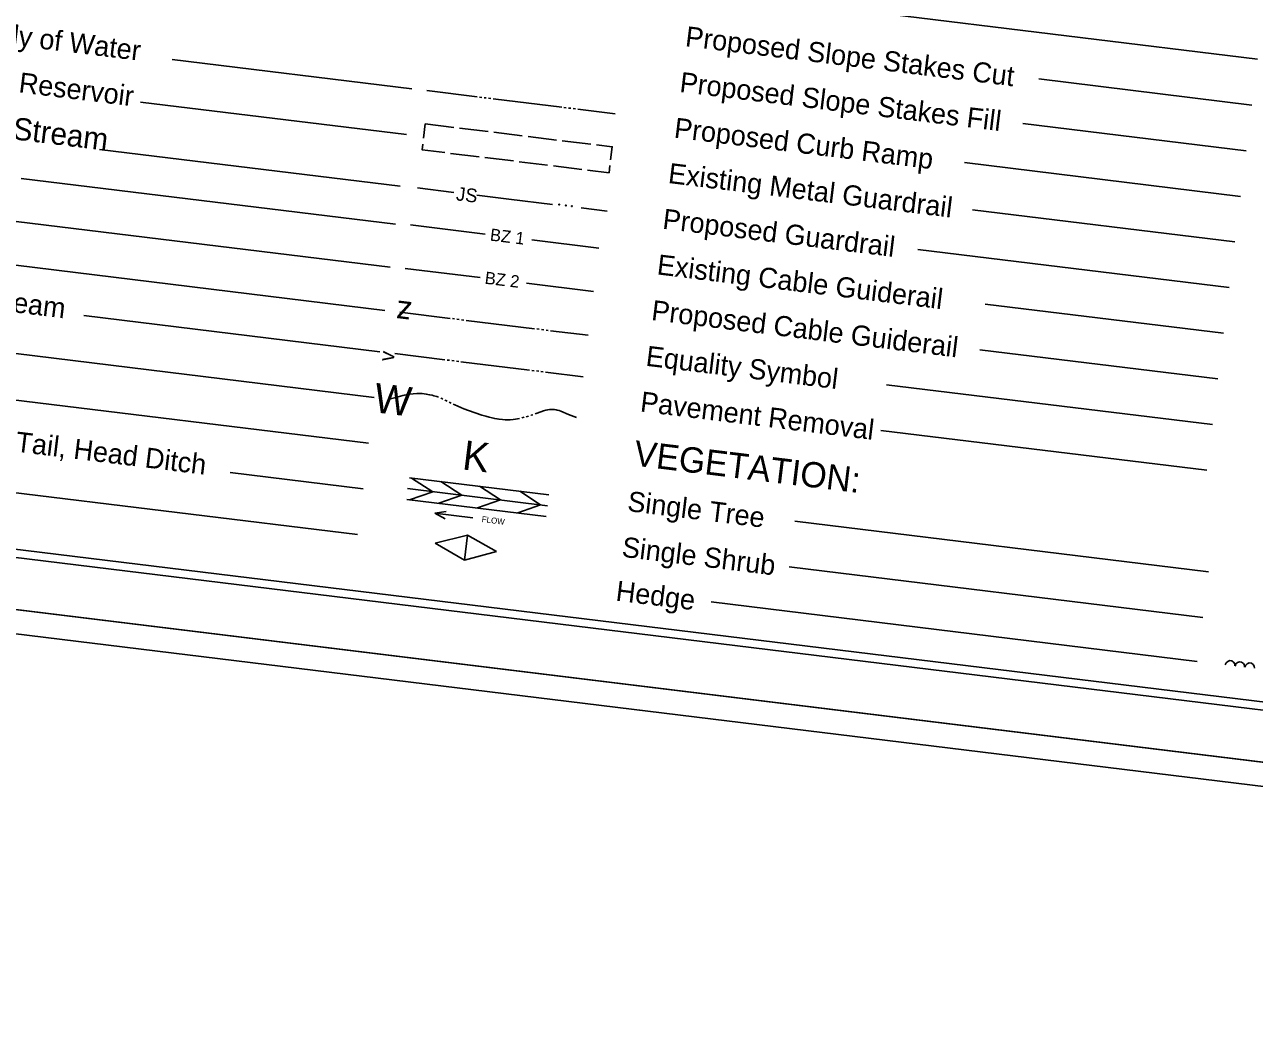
# Model space of a CAD drawing. Extents: x 1756435 to 1766932, y 416863 to 426859.
# Drawn here: x 1759938 to 1762075, y 416863 to 418599 of the extents above; entities that cross this region are included whole.
import ezdxf

# ---------------------------------------------------------------- set-up
doc = ezdxf.new("R2010")
doc.units = 0
for name, color, linetype in [('Scratch_Level_2', 7, 'Continuous'), ('Sheet Cutting Line CELL', 7, 'Continuous'), ('Sheet Plot Border Inside CELL', 7, 'Continuous'), ('Sheet Plot Border Outside CELL', 7, 'Continuous'), ('Sheet Symbology CELL', 7, 'Continuous')]:
    doc.layers.add(name, color=color, linetype=linetype)

msp = doc.modelspace()

# ---------------------------------------------------------------- linework, layer by layer
at = {"layer": 'Scratch_Level_2'}
msp.add_lwpolyline([(1759243.8, 422098.1), (1765929.9, 421280), (1765395.5, 416912.5), (1758709.3, 417730.7)], close=True, dxfattribs=at)
at = {"layer": 'Sheet Cutting Line CELL'}
for p, q in [((1758709.3, 417730.7), (1765395.5, 416912.5)), ((1758704.3, 417689.2), (1765453.9, 416863.3))]:
    msp.add_line(p, q, dxfattribs=at)
at = {"layer": 'Sheet Plot Border Inside CELL'}
msp.add_lwpolyline([(1758771.9, 417813.5), (1765388.5, 417003.9), (1765901.1, 421193), (1759284.5, 422002.7)], close=True, dxfattribs=at)
at = {"layer": 'Sheet Plot Border Outside CELL'}
msp.add_lwpolyline([(1758709.3, 417730.7), (1765395.5, 416912.5), (1765929.9, 421280), (1759243.8, 422098.1)], close=True, dxfattribs=at)
at = {"layer": 'Sheet Symbology CELL'}
for p, q in [((1762080, 418538.6), (1761416.3, 418619.8)), ((1760610.7, 418487.2), (1760193.8, 418538.2)), ((1762070.3, 418459.1), (1761700.3, 418504.4)), ((1760636.6, 418484.1), (1760724, 418473.4)), ((1760728, 418472.9), (1760732, 418472.4)), ((1760735.9, 418471.9), (1760739.9, 418471.4)), ((1760743.9, 418470.9), (1760747.8, 418470.4)), ((1760751.8, 418470), (1760870.9, 418455.4)), ((1760601, 418407.8), (1760138.9, 418464.4)), ((1760874.9, 418454.9), (1760878.9, 418454.4)), ((1760882.8, 418453.9), (1760886.8, 418453.4)), ((1760890.8, 418452.9), (1760894.7, 418452.5)), ((1760898.7, 418452), (1760964.1, 418444)), ((1760630.7, 418401.3), (1760633.8, 418426.3)), ((1760633.8, 418426.3), (1760683.4, 418420.2)), ((1762060.6, 418379.7), (1761672.5, 418427.2)), ((1760693.3, 418419), (1760743, 418412.9)), ((1760752.9, 418411.7), (1760802.5, 418405.6)), ((1760812.4, 418404.4), (1760862.1, 418398.3)), ((1760872, 418397.1), (1760921.6, 418391)), ((1760590, 418318.1), (1760067.5, 418382)), ((1760727.4, 418369.2), (1760677.8, 418375.2)), ((1760787, 418361.9), (1760737.4, 418368)), ((1760846.5, 418354.6), (1760796.9, 418360.7)), ((1760906.1, 418347.3), (1760856.5, 418353.4)), ((1762050.8, 418300.3), (1761570.7, 418359.1)), ((1760581.9, 418252.1), (1759931.8, 418331.7)), ((1762040.6, 418221.5), (1761584.6, 418277.3)), ((1760572.8, 418177.2), (1759922.6, 418256.8)), ((1760608, 418250.7), (1760738.2, 418234.7)), ((1760935.6, 418210.6), (1760819.2, 418224.8)), ((1762030.8, 418142.1), (1761489.9, 418208.3)), ((1760563.6, 418102.3), (1759849.6, 418189.7)), ((1760598.8, 418175.3), (1760729, 418159.4)), ((1760926.3, 418135.2), (1760810, 418149.5)), ((1762021.1, 418062.7), (1761607, 418113.3)), ((1760554.8, 418030.3), (1760040.6, 418093.3)), ((1760589.5, 418099.1), (1760676.9, 418088.4)), ((1760680.9, 418087.9), (1760684.9, 418087.4)), ((1760688.8, 418087), (1760692.8, 418086.5)), ((1760696.8, 418086), (1760700.7, 418085.5)), ((1760704.7, 418085), (1760823.8, 418070.4)), ((1760827.8, 418070), (1760831.8, 418069.5)), ((1760835.7, 418069), (1760839.7, 418068.5)), ((1760843.7, 418068), (1760847.6, 418067.5)), ((1760851.6, 418067), (1760917, 418059)), ((1760545.1, 417950.9), (1759709.4, 418053.2)), ((1760580.7, 418027.2), (1760668.1, 418016.5)), ((1762011.4, 417983.3), (1761597.3, 418033.9)), ((1760672.1, 418016), (1760676.1, 418015.5)), ((1760680, 418015), (1760684, 418014.5)), ((1760688, 418014), (1760691.9, 418013.6)), ((1760695.9, 418013.1), (1760815, 417998.5)), ((1760819, 417998), (1760823, 417997.5)), ((1760826.9, 417997), (1760830.9, 417996.6)), ((1760834.9, 417996.1), (1760838.8, 417995.6)), ((1760842.8, 417995.1), (1760908.2, 417987.1)), ((1760535.4, 417871.5), (1759768.2, 417965.4)), ((1762001.7, 417903.8), (1761435.4, 417973.1)), ((1760675.2, 417942.9), (1760678.8, 417941.1)), ((1760801.6, 417915.6), (1760805.5, 417916.7)), ((1760809.4, 417917.6), (1760813.2, 417918.7)), ((1761992, 417824.4), (1761425.7, 417893.7)), ((1760525.7, 417792.1), (1760294.7, 417820.4)), ((1760606.5, 417811.4), (1760848.8, 417781.8)), ((1760610.1, 417811), (1760646.7, 417787.2)), ((1760515.9, 417712.7), (1759800.2, 417800.3)), ((1760603.2, 417792.5), (1760846.5, 417762.7)), ((1760646.7, 417787.2), (1760606.6, 417773.3)), ((1760660.6, 417804.8), (1760697.1, 417781)), ((1760727.9, 417796.6), (1760764.6, 417772.8)), ((1760798.3, 417788), (1760834.1, 417764.2)), ((1760602, 417773.9), (1760844.2, 417744.3)), ((1760697.1, 417781), (1760657.2, 417767.2)), ((1760764.6, 417772.8), (1760724.7, 417758.9)), ((1760834.1, 417764.2), (1760794.8, 417750.3)), ((1760650.4, 417749.9), (1760670.1, 417752.9)), ((1760650.4, 417749.9), (1760716.5, 417741.8)), ((1760650.4, 417749.9), (1760668.5, 417739.8)), ((1761995.1, 417648.2), (1761276, 417736.2)), ((1760707.5, 417711.9), (1760651, 417697.5)), ((1760702.1, 417668), (1760707.5, 417711.9)), ((1760757.6, 417683.5), (1760707.5, 417711.9)), ((1760651, 417697.5), (1760702.1, 417668)), ((1760702.1, 417668), (1760757.6, 417683.5)), ((1761985.4, 417568.8), (1761266.3, 417656.8)), ((1761975, 417492.4), (1761130.5, 417595.8)), ((1762024.2, 417486.4), (1762025.9, 417490)), ((1762025.9, 417490), (1762028.6, 417492.3)), ((1762028.6, 417492.3), (1762031.9, 417493.7)), ((1762031.9, 417493.7), (1762035.7, 417493.3)), ((1762035.7, 417493.3), (1762038.7, 417490.9)), ((1762038.7, 417490.9), (1762040.5, 417488)), ((1762040.5, 417488), (1762040.9, 417484.6)), ((1762041.1, 417484.3), (1762042.7, 417488)), ((1762042.7, 417488), (1762045.4, 417490.3)), ((1762045.4, 417490.3), (1762048.8, 417491.7)), ((1762048.8, 417491.7), (1762052.6, 417491.2)), ((1762052.6, 417491.2), (1762055.5, 417488.8)), ((1762055.5, 417488.8), (1762057.4, 417486)), ((1762057.4, 417486), (1762057.8, 417482.5)), ((1762058, 417482.3), (1762059.6, 417485.9)), ((1762059.6, 417485.9), (1762062.3, 417488.2)), ((1762062.3, 417488.2), (1762065.7, 417489.6)), ((1762065.7, 417489.6), (1762069.5, 417489.1)), ((1762069.5, 417489.1), (1762072.4, 417486.8)), ((1762072.4, 417486.8), (1762074.3, 417483.9)), ((1762074.3, 417483.9), (1762074.7, 417480.4))]:
    msp.add_line(p, q, dxfattribs=at)
msp.add_lwpolyline([(1765850.3, 421189), (1759894.7, 421917.7), (1759385, 417752.9), (1765340.6, 417024.1)], close=True, dxfattribs=at)
for points in [[(1760667.9, 418376.5), (1760628.3, 418381.3), (1760629.5, 418391.3)], [(1760931.6, 418389.8), (1760958.7, 418386.5), (1760955.9, 418364)], [(1760954.7, 418354.1), (1760953.2, 418341.5), (1760916, 418346.1)], [(1760620.2, 418315.2), (1760683.7, 418307.4)], [(1760723.6, 418302.5), (1760779.3, 418295.7)], [(1760779.3, 418295.7), (1760854.7, 418286.5)], [(1760904.7, 418280.4), (1760950, 418274.8)], [(1760571, 417947.8), (1760582.8, 417951.1), (1760594.7, 417954.5), (1760597.7, 417955.2), (1760602.9, 417956.4), (1760606.9, 417956.9), (1760612.9, 417957.5), (1760618.9, 417957.9), (1760623.9, 417957.9), (1760628.3, 417957.7), (1760632.1, 417957.3), (1760635.5, 417956.9), (1760641.3, 417955.8), (1760645.7, 417954.8), (1760648.9, 417953.9), (1760653.7, 417952.4), (1760657, 417951.2)], [(1760660.7, 417949.7), (1760662.5, 417948.9), (1760664.4, 417948.1)], [(1760668, 417946.4), (1760669.6, 417945.6), (1760671.6, 417944.6)], [(1760682.4, 417939.4), (1760685.3, 417938), (1760690.7, 417935.6), (1760701, 417931.5), (1760708.8, 417928.5), (1760720.5, 417924.2), (1760732.3, 417920.2), (1760738.9, 417918.2), (1760744.8, 417916.6), (1760750, 417915.3), (1760754.5, 417914.4), (1760758.5, 417913.7), (1760762.1, 417913.1), (1760768.3, 417912.5), (1760772.9, 417912.2), (1760776.4, 417912.2), (1760781.6, 417912.3), (1760786.8, 417912.8), (1760790.8, 417913.4), (1760794.2, 417913.9), (1760797.7, 417914.7)], [(1760817, 417919.8), (1760817.9, 417920.1), (1760820.8, 417921)], [(1760824.6, 417922.4), (1760826.6, 417923.1), (1760834.9, 417926.2), (1760839.1, 417927.6), (1760843.5, 417928.8), (1760846.7, 417929.5), (1760849.6, 417929.8), (1760852.1, 417930), (1760854.3, 417930.1), (1760858.3, 417929.9), (1760861.1, 417929.5), (1760863.2, 417929.1), (1760866.4, 417928.3), (1760869.4, 417927.2), (1760883, 417921.6), (1760896.6, 417916)]]:
    msp.add_lwpolyline(points, dxfattribs=at)
for centre in [(1760866.5, 418286.2), (1760878.3, 418284.7), (1760888.5, 418283.5)]:
    msp.add_ellipse(centre, major_axis=(0.096, 0.782), ratio=0.938496, dxfattribs=at)

# ---------------------------------------------------------------- texts
for s, height, rotation, p in [('Stream or Body of Water', 35, 353.0234, (1759626, 418598.6)), ('Proposed Slope Stakes Cut', 35, 353.0234, (1761084.4, 418561.5)), ('Hydro, Pool or Reservoir', 35, 353.0234, (1759616.3, 418519.2)), ('Proposed Slope Stakes Fill', 35, 353.0234, (1761074.7, 418482)), ('Jurisdictional Stream', 38.584, 353.0234, (1759605, 418437.8)), ('Proposed Curb Ramp', 35, 353.0234, (1761065, 418402.6)), ('Existing Metal Guardrail', 35, 353.0234, (1761054.7, 418323.8)), ('JS', 23.62, 353.0234, (1760686.5, 418293.7)), ('Proposed Guardrail', 35, 353.0234, (1761045, 418244.4)), ('BZ 1', 21.26, 353.0234, (1760745.5, 418223.7)), ('Existing Cable Guiderail', 35, 353.0234, (1761035.3, 418165)), ('Disappearing Stream', 35, 353.0234, (1759570.1, 418141.7)), ('BZ 2', 21.26, 353.0234, (1760736.4, 418148.7)), ('z', 40, 173.0234, (1760611.8, 418116.5)), ('Proposed Cable Guiderail', 35, 353.0234, (1761025.6, 418085.6)), ('v', 26.4, 82.7825, (1760578.8, 418012.3)), ('Equality Symbol', 35, 353.0234, (1761015.9, 418006.2)), ('W', 51, 353.0234, (1760542.6, 417925.6)), ('Pavement Removal', 35, 353.0234, (1761006.2, 417926.8)), ('Proposed Lateral, Tail, Head Ditch', 35, 353.0234, (1759540.9, 417903.5)), ('K', 51, 353.0234, (1760696.6, 417826.1)), ('VEGETATION:', 44, 353.0234, (1760994.6, 417832.9)), ('Single Tree', 35, 353.0234, (1760983.8, 417753.7)), ('FLOW', 10.37, 353.0234, (1760731.5, 417734.5)), ('Single Shrub', 35, 353.0234, (1760974.1, 417674.3)), ('Hedge', 35, 353.0234, (1760963.7, 417598))]:
    msp.add_text(s, height=height, rotation=rotation, dxfattribs=at).set_placement(p)

doc.saveas('drawing.dxf')
